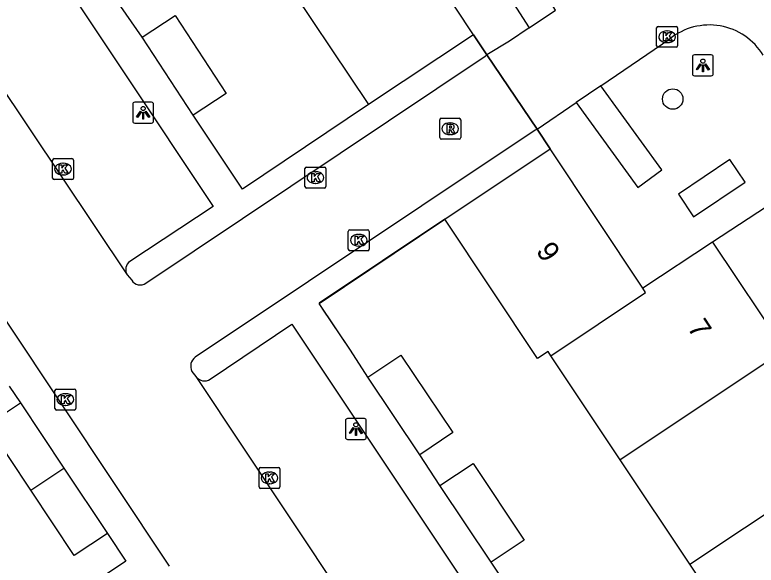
# Model space of a CAD drawing. Extents: x 158352 to 159489, y 383828 to 384597.
# Drawn here: x 158738.01 to 158773.43, y 384230.08 to 384256.39 of the extents above; entities that cross this region are included whole.
import ezdxf

# ---------------------------------------------------------------- set-up
doc = ezdxf.new("R2010")
doc.units = 0
for name, color, linetype in [('IMGEO_Boom', 7, 'Continuous'), ('IMGEO_Hek', 7, 'Continuous'), ('IMGEO_Kolk', 7, 'Continuous'), ('IMGEO_Lichtpunt', 7, 'Continuous'), ('IMGEO_Muur', 7, 'Continuous'), ('IMGEO_Pand', 7, 'Continuous'), ('IMGEO_Pand_nummerreeks', 7, 'Continuous'), ('IMGEO_Rijbaan_lokaal_open', 7, 'Continuous'), ('IMGEO_Rioolput', 7, 'Continuous'), ('IMGEO_Voetpad_open', 7, 'Continuous')]:
    doc.layers.add(name, color=color, linetype=linetype)

msp = doc.modelspace()

# ---------------------------------------------------------------- linework, layer by layer
at = {"layer": 'IMGEO_Boom'}
msp.add_circle((158769.446, 384252.366), 0.489, dxfattribs=at)
at = {"layer": 'IMGEO_Hek'}
for points in [[(158759.926, 384255.435), (158760.57, 384254.474)], [(158760.57, 384254.474), (158762.961, 384250.932)], [(158762.961, 384250.932), (158763.582, 384249.979)]]:
    msp.add_lwpolyline(points, dxfattribs=at)
at = {"layer": 'IMGEO_Kolk'}
for p, q in [((158768.677, 384254.916), (158768.677, 384255.768)), ((158768.752, 384255.842), (158769.604, 384255.842)), ((158769.165, 384255.622), (158769.19, 384255.622)), ((158769.678, 384255.768), (158769.678, 384254.916)), ((158769.604, 384254.842), (158768.752, 384254.842)), ((158769.188, 384255.062), (158769.163, 384255.062)), ((158739.884, 384249.516), (158740.736, 384249.516)), ((158739.809, 384248.59), (158739.809, 384249.442)), ((158740.297, 384249.296), (158740.322, 384249.296)), ((158740.81, 384249.442), (158740.81, 384248.59)), ((158751.871, 384248.186), (158751.871, 384249.038)), ((158751.946, 384249.112), (158752.798, 384249.112)), ((158752.359, 384248.892), (158752.384, 384248.892)), ((158752.872, 384249.038), (158752.872, 384248.186)), ((158740.736, 384248.516), (158739.884, 384248.516)), ((158740.32, 384248.736), (158740.295, 384248.736)), ((158752.798, 384248.112), (158751.946, 384248.112)), ((158752.382, 384248.332), (158752.357, 384248.332)), ((158753.943, 384245.189), (158753.943, 384246.041)), ((158754.018, 384246.115), (158754.87, 384246.115)), ((158754.944, 384246.041), (158754.944, 384245.189)), ((158754.431, 384245.895), (158754.456, 384245.895)), ((158754.454, 384245.335), (158754.429, 384245.335)), ((158754.87, 384245.115), (158754.018, 384245.115)), ((158739.921, 384237.573), (158739.921, 384238.425)), ((158739.996, 384238.499), (158740.848, 384238.499)), ((158740.409, 384238.279), (158740.434, 384238.279)), ((158740.922, 384238.425), (158740.922, 384237.573)), ((158740.848, 384237.499), (158739.996, 384237.499)), ((158740.432, 384237.719), (158740.407, 384237.719)), ((158749.675, 384233.827), (158749.675, 384234.679)), ((158749.75, 384234.753), (158750.602, 384234.753)), ((158750.676, 384234.679), (158750.676, 384233.827)), ((158750.163, 384234.533), (158750.188, 384234.533)), ((158750.186, 384233.973), (158750.161, 384233.973)), ((158750.602, 384233.753), (158749.75, 384233.753))]:
    msp.add_line(p, q, dxfattribs=at)
for points in [[(158768.677, 384254.916), (158768.677, 384255.768)], [(158768.752, 384255.842), (158769.604, 384255.842)], [(158768.998, 384255.542), (158769.121, 384255.542), (158769.121, 384255.391), (158769.251, 384255.542), (158769.415, 384255.542), (158769.269, 384255.391), (158769.422, 384255.142), (158769.27, 384255.142), (158769.185, 384255.306), (158769.121, 384255.239), (158769.121, 384255.142), (158768.998, 384255.142), (158768.998, 384255.542)], [(158769.678, 384255.768), (158769.678, 384254.916)], [(158769.604, 384254.842), (158768.752, 384254.842)], [(158739.884, 384249.516), (158740.736, 384249.516)], [(158739.809, 384248.59), (158739.809, 384249.442)], [(158740.13, 384249.216), (158740.253, 384249.216), (158740.253, 384249.065), (158740.383, 384249.216), (158740.547, 384249.216), (158740.401, 384249.065), (158740.554, 384248.816), (158740.402, 384248.816), (158740.317, 384248.98), (158740.253, 384248.913), (158740.253, 384248.816), (158740.13, 384248.816), (158740.13, 384249.216)], [(158740.81, 384249.442), (158740.81, 384248.59)], [(158751.871, 384248.186), (158751.871, 384249.038)], [(158751.946, 384249.112), (158752.798, 384249.112)], [(158752.192, 384248.812), (158752.315, 384248.812), (158752.315, 384248.661), (158752.445, 384248.812), (158752.609, 384248.812), (158752.463, 384248.661), (158752.616, 384248.412), (158752.464, 384248.412), (158752.379, 384248.576), (158752.315, 384248.509), (158752.315, 384248.412), (158752.192, 384248.412), (158752.192, 384248.812)], [(158752.872, 384249.038), (158752.872, 384248.186)], [(158740.736, 384248.516), (158739.884, 384248.516)], [(158752.798, 384248.112), (158751.946, 384248.112)], [(158753.943, 384245.189), (158753.943, 384246.041)], [(158754.018, 384246.115), (158754.87, 384246.115)], [(158754.944, 384246.041), (158754.944, 384245.189)], [(158754.264, 384245.815), (158754.387, 384245.815), (158754.387, 384245.664), (158754.517, 384245.815), (158754.681, 384245.815), (158754.535, 384245.664), (158754.688, 384245.415), (158754.536, 384245.415), (158754.451, 384245.579), (158754.387, 384245.512), (158754.387, 384245.415), (158754.264, 384245.415), (158754.264, 384245.815)], [(158754.87, 384245.115), (158754.018, 384245.115)], [(158739.921, 384237.573), (158739.921, 384238.425)], [(158739.996, 384238.499), (158740.848, 384238.499)], [(158740.242, 384238.199), (158740.365, 384238.199), (158740.365, 384238.048), (158740.495, 384238.199), (158740.659, 384238.199), (158740.513, 384238.048), (158740.666, 384237.799), (158740.514, 384237.799), (158740.429, 384237.963), (158740.365, 384237.896), (158740.365, 384237.799), (158740.242, 384237.799), (158740.242, 384238.199)], [(158740.922, 384238.425), (158740.922, 384237.573)], [(158740.848, 384237.499), (158739.996, 384237.499)], [(158749.675, 384233.827), (158749.675, 384234.679)], [(158749.75, 384234.753), (158750.602, 384234.753)], [(158750.676, 384234.679), (158750.676, 384233.827)], [(158749.996, 384234.453), (158750.119, 384234.453), (158750.119, 384234.302), (158750.249, 384234.453), (158750.413, 384234.453), (158750.267, 384234.302), (158750.42, 384234.053), (158750.268, 384234.053), (158750.183, 384234.217), (158750.119, 384234.15), (158750.119, 384234.053), (158749.996, 384234.053), (158749.996, 384234.453)], [(158750.602, 384233.753), (158749.75, 384233.753)]]:
    msp.add_lwpolyline(points, dxfattribs=at)
for centre, start, end in [((158768.754, 384255.766), 91.552, 178.448), ((158768.754, 384255.766), 91.552, 178.448), ((158769.602, 384255.766), 1.552, 88.448), ((158769.602, 384255.766), 1.552, 88.448), ((158768.754, 384254.918), 181.552, 268.448), ((158768.754, 384254.918), 181.552, 268.448), ((158769.602, 384254.918), 271.552, 358.448), ((158769.602, 384254.918), 271.552, 358.448), ((158739.886, 384249.44), 91.552, 178.448), ((158739.886, 384249.44), 91.552, 178.448), ((158740.734, 384249.44), 1.552, 88.448), ((158740.734, 384249.44), 1.552, 88.448), ((158751.948, 384249.036), 91.552, 178.448), ((158751.948, 384249.036), 91.552, 178.448), ((158752.796, 384249.036), 1.552, 88.448), ((158752.796, 384249.036), 1.552, 88.448), ((158739.886, 384248.592), 181.552, 268.448), ((158739.886, 384248.592), 181.552, 268.448), ((158740.734, 384248.592), 271.552, 358.448), ((158740.734, 384248.592), 271.552, 358.448), ((158751.948, 384248.188), 181.552, 268.448), ((158751.948, 384248.188), 181.552, 268.448), ((158752.796, 384248.188), 271.552, 358.448), ((158752.796, 384248.188), 271.552, 358.448), ((158754.02, 384246.039), 91.552, 178.448), ((158754.02, 384246.039), 91.552, 178.448), ((158754.868, 384246.039), 1.552, 88.448), ((158754.868, 384246.039), 1.552, 88.448), ((158754.02, 384245.191), 181.552, 268.448), ((158754.02, 384245.191), 181.552, 268.448), ((158754.868, 384245.191), 271.552, 358.448), ((158754.868, 384245.191), 271.552, 358.448), ((158739.998, 384238.423), 91.552, 178.448), ((158739.998, 384238.423), 91.552, 178.448), ((158740.846, 384238.423), 1.552, 88.448), ((158740.846, 384238.423), 1.552, 88.448), ((158739.998, 384237.575), 181.552, 268.448), ((158739.998, 384237.575), 181.552, 268.448), ((158740.846, 384237.575), 271.552, 358.448), ((158740.846, 384237.575), 271.552, 358.448), ((158749.752, 384234.677), 91.552, 178.448), ((158749.752, 384234.677), 91.552, 178.448), ((158750.6, 384234.677), 1.552, 88.448), ((158750.6, 384234.677), 1.552, 88.448), ((158749.752, 384233.829), 181.552, 268.448), ((158749.752, 384233.829), 181.552, 268.448), ((158750.6, 384233.829), 271.552, 358.448), ((158750.6, 384233.829), 271.552, 358.448)]:
    msp.add_arc(centre, 0.0765, start, end, dxfattribs=at)
for centre, major_axis, ratio, start_param, end_param in [((158769.164, 384255.342), (-0.387, 0.002), 0.722429, 4.712389, 7.853982), ((158769.189, 384255.342), (-0.39, 0.002), 0.717154, 1.570796, 4.712389), ((158740.296, 384249.016), (-0.387, 0.002), 0.722429, 4.712389, 7.853982), ((158740.321, 384249.016), (-0.39, 0.002), 0.717154, 1.570796, 4.712389), ((158752.358, 384248.612), (-0.387, 0.002), 0.722429, 4.712389, 7.853982), ((158752.383, 384248.612), (-0.39, 0.002), 0.717154, 1.570796, 4.712389), ((158754.43, 384245.615), (-0.387, 0.002), 0.722429, 4.712389, 7.853982), ((158754.455, 384245.615), (-0.39, 0.002), 0.717154, 1.570796, 4.712389), ((158740.408, 384237.999), (-0.387, 0.002), 0.722429, 4.712389, 7.853982), ((158740.433, 384237.999), (-0.39, 0.002), 0.717154, 1.570796, 4.712389), ((158750.162, 384234.253), (-0.387, 0.002), 0.722429, 4.712389, 7.853982), ((158750.187, 384234.253), (-0.39, 0.002), 0.717154, 1.570796, 4.712389)]:
    msp.add_ellipse(centre, major_axis=major_axis, ratio=ratio, start_param=start_param, end_param=end_param, dxfattribs=at)
at = {"layer": 'IMGEO_Lichtpunt'}
for p, q in [((158771.289, 384254.476), (158770.481, 384254.476)), ((158771.289, 384254.476), (158770.481, 384254.476)), ((158770.387, 384254.381), (158770.387, 384253.574)), ((158770.387, 384254.381), (158770.387, 384253.574)), ((158771.383, 384253.574), (158771.383, 384254.381)), ((158771.383, 384253.574), (158771.383, 384254.381)), ((158770.481, 384253.48), (158771.289, 384253.48)), ((158770.481, 384253.48), (158771.289, 384253.48)), ((158743.64, 384252.117), (158743.64, 384251.31)), ((158743.64, 384252.117), (158743.64, 384251.31)), ((158744.542, 384252.212), (158743.734, 384252.212)), ((158744.542, 384252.212), (158743.734, 384252.212)), ((158744.636, 384251.31), (158744.636, 384252.117)), ((158744.636, 384251.31), (158744.636, 384252.117)), ((158743.734, 384251.216), (158744.542, 384251.216)), ((158743.734, 384251.216), (158744.542, 384251.216)), ((158753.807, 384236.994), (158753.807, 384236.187)), ((158753.807, 384236.994), (158753.807, 384236.187)), ((158754.709, 384237.089), (158753.901, 384237.089)), ((158754.709, 384237.089), (158753.901, 384237.089)), ((158754.803, 384236.187), (158754.803, 384236.994)), ((158754.803, 384236.187), (158754.803, 384236.994)), ((158753.901, 384236.093), (158754.709, 384236.093)), ((158753.901, 384236.093), (158754.709, 384236.093))]:
    msp.add_line(p, q, dxfattribs=at)
for points in [[(158770.761, 384254.045), (158770.8, 384254.017), (158770.612, 384253.755), (158770.574, 384253.782), (158770.761, 384254.045)], [(158770.863, 384253.997), (158770.91, 384253.997), (158770.91, 384253.675), (158770.863, 384253.675), (158770.863, 384253.997)], [(158770.973, 384254.017), (158771.011, 384254.044), (158771.198, 384253.782), (158771.159, 384253.754), (158770.973, 384254.017)], [(158744.014, 384251.781), (158744.053, 384251.753), (158743.865, 384251.491), (158743.827, 384251.518), (158744.014, 384251.781)], [(158744.116, 384251.733), (158744.163, 384251.733), (158744.163, 384251.411), (158744.116, 384251.411), (158744.116, 384251.733)], [(158744.226, 384251.753), (158744.264, 384251.78), (158744.451, 384251.518), (158744.412, 384251.49), (158744.226, 384251.753)], [(158754.181, 384236.658), (158754.22, 384236.63), (158754.032, 384236.368), (158753.994, 384236.395), (158754.181, 384236.658)], [(158754.283, 384236.61), (158754.33, 384236.61), (158754.33, 384236.288), (158754.283, 384236.288), (158754.283, 384236.61)], [(158754.393, 384236.63), (158754.431, 384236.657), (158754.618, 384236.395), (158754.579, 384236.367), (158754.393, 384236.63)]]:
    msp.add_lwpolyline(points, dxfattribs=at)
for centre in [(158770.886, 384254.179), (158744.139, 384251.915), (158754.306, 384236.792)]:
    msp.add_circle(centre, 0.0994, dxfattribs=at)
for centre, start, end in [((158770.481, 384254.381), 90, 180), ((158770.481, 384254.381), 90, 180), ((158771.289, 384254.381), 0, 90), ((158771.289, 384254.381), 0, 90), ((158770.481, 384253.574), 180, 270), ((158770.481, 384253.574), 180, 270), ((158771.289, 384253.574), 270, 0), ((158771.289, 384253.574), 270, 360), ((158743.734, 384252.117), 90, 180), ((158743.734, 384252.117), 90, 180), ((158744.542, 384252.117), 0, 90), ((158744.542, 384252.117), 0, 90), ((158743.734, 384251.31), 180, 270), ((158743.734, 384251.31), 180, 270), ((158744.542, 384251.31), 270, 0), ((158744.542, 384251.31), 270, 360), ((158753.901, 384236.994), 90, 180), ((158753.901, 384236.994), 90, 180), ((158754.709, 384236.994), 0, 90), ((158754.709, 384236.994), 0, 90), ((158753.901, 384236.187), 180, 270), ((158753.901, 384236.187), 180, 270), ((158754.709, 384236.187), 270, 0), ((158754.709, 384236.187), 270, 360)]:
    msp.add_arc(centre, 0.0946, start, end, dxfattribs=at)
at = {"layer": 'IMGEO_Muur'}
for points in [[(158754.903, 384252.103), (158748.889, 384248.062), (158747.381, 384250.297)], [(158754.054, 384240.358), (158752.543, 384242.59), (158758.557, 384246.623)], [(158758.557, 384246.623), (158752.557, 384242.6)], [(158754.054, 384240.358), (158752.691, 384242.371)]]:
    msp.add_lwpolyline(points, dxfattribs=at)
at = {"layer": 'IMGEO_Pand'}
for points in [[(158759.926, 384255.435), (158755.506, 384262.112)], [(158750.839, 384259.277), (158750.964, 384259.082), (158750.465, 384258.749), (158754.903, 384252.103)], [(158744.096, 384255.329), (158745.673, 384256.358), (158748.107, 384252.627), (158746.53, 384251.598)], [(158746.53, 384251.598), (158744.096, 384255.329)], [(158759.926, 384255.435), (158754.903, 384252.103)], [(158758.557, 384246.623), (158763.582, 384249.979)], [(158768.012, 384243.32), (158763.582, 384249.979)], [(158763.624, 384240.093), (158763.486, 384240.292), (158762.986, 384239.96), (158758.557, 384246.623)], [(158771.344, 384245.523), (158768.012, 384243.32)], [(158771.344, 384245.523), (158774.797, 384240.358)], [(158763.624, 384240.093), (158768.148, 384243.116), (158768.012, 384243.32)], [(158774.797, 384240.358), (158766.937, 384235.12)], [(158754.871, 384239.063), (158756.447, 384240.124), (158758.936, 384236.423), (158757.36, 384235.363)], [(158766.937, 384235.12), (158763.624, 384240.093)], [(158757.36, 384235.363), (158754.871, 384239.063)], [(158738.77, 384233.665), (158736.691, 384236.783), (158738.272, 384237.837)], [(158738.272, 384237.837), (158740.351, 384234.719)], [(158770.27, 384230.127), (158778.142, 384235.374)], [(158770.27, 384230.127), (158766.937, 384235.12)], [(158738.77, 384233.665), (158740.351, 384234.719)], [(158740.351, 384234.719), (158742.43, 384231.601)], [(158758.322, 384233.895), (158759.903, 384234.949), (158762.351, 384231.275), (158760.77, 384230.221)], [(158742.43, 384231.601), (158740.849, 384230.547), (158738.77, 384233.665)], [(158760.77, 384230.221), (158758.322, 384233.895)], [(158773.591, 384225.148), (158770.27, 384230.127)]]:
    msp.add_lwpolyline(points, dxfattribs=at)
at = {"layer": 'IMGEO_Rijbaan_lokaal_open'}
for points in [[(158726.176, 384269.689), (158743.37, 384243.965)], [(158762.589, 384255.767), (158763.847, 384256.62)], [(158762.589, 384255.767), (158761.652, 384255.133), (158760.57, 384254.474)], [(158766.013, 384253.005), (158769.3, 384255.239)], [(158744.263, 384243.568), (158760.476, 384254.416), (158760.57, 384254.474)], [(158762.961, 384250.932), (158760.57, 384254.474)], [(158766.013, 384253.005), (158764.828, 384252.201)], [(158762.961, 384250.932), (158764.828, 384252.201)], [(158762.961, 384250.932), (158762.876, 384250.875), (158746.627, 384240.029)], [(158745.402, 384230.033), (158735.025, 384245.603)], [(158743.37, 384243.965), (158743.597, 384243.711)], [(158746.472, 384239.345), (158746.663, 384239.098)], [(158746.663, 384239.098), (158765.045, 384211.446)]]:
    msp.add_lwpolyline(points, dxfattribs=at)
for centre, radius, start, end in [((158771.193, 384252.892), 3.015, 31.2892, 128.885), ((158743.992, 384243.927), 0.45, 208.6552, 307.1083), ((158746.948, 384239.597), 0.539, 126.6135, 207.8504)]:
    msp.add_arc(centre, radius, start, end, dxfattribs=at)
at = {"layer": 'IMGEO_Rioolput'}
for p, q in [((158758.311, 384250.521), (158758.311, 384251.373)), ((158758.386, 384251.447), (158759.238, 384251.447)), ((158759.312, 384251.373), (158759.312, 384250.521)), ((158758.799, 384251.227), (158758.824, 384251.227)), ((158758.822, 384250.667), (158758.797, 384250.667)), ((158759.238, 384250.447), (158758.386, 384250.447))]:
    msp.add_line(p, q, dxfattribs=at)
for points in [[(158758.311, 384250.521), (158758.311, 384251.373)], [(158758.386, 384251.447), (158759.238, 384251.447)], [(158759.312, 384251.373), (158759.312, 384250.521)], [(158758.9, 384251.145), (158758.648, 384251.147), (158758.648, 384250.747)], [(158758.826, 384251.066), (158758.772, 384251.066), (158758.772, 384250.985)], [(158758.772, 384250.985), (158758.824, 384250.985)], [(158758.648, 384250.747), (158758.772, 384250.747), (158758.772, 384250.909), (158758.783, 384250.909)], [(158758.83, 384250.88), (158758.901, 384250.747), (158759.041, 384250.747), (158758.976, 384250.873)], [(158759.238, 384250.447), (158758.386, 384250.447)]]:
    msp.add_lwpolyline(points, dxfattribs=at)
for centre, radius, start, end in [((158758.388, 384251.371), 0.0765, 91.552, 178.448), ((158758.388, 384251.371), 0.0765, 91.552, 178.448), ((158759.236, 384251.371), 0.0765, 1.552, 88.448), ((158759.236, 384251.371), 0.0765, 1.552, 88.448), ((158758.808, 384251.174), 0.19, 274.7715, 282.9687), ((158758.832, 384250.97), 0.0964, 77.0061, 93.1865), ((158758.846, 384251.027), 0.0378, 276.6634, 79.6772), ((158758.899, 384251.035), 0.109, 350.3612, 89.416), ((158758.897, 384251.035), 0.112, 277.5842, 350.9817), ((158758.881, 384250.82), 0.108, 29.5134, 73.7905), ((158758.782, 384250.856), 0.0533, 26.0293, 88.6989), ((158758.388, 384250.523), 0.0765, 181.552, 268.448), ((158758.388, 384250.523), 0.0765, 181.552, 268.448), ((158759.236, 384250.523), 0.0765, 271.552, 358.448), ((158759.236, 384250.523), 0.0765, 271.552, 358.448)]:
    msp.add_arc(centre, radius, start, end, dxfattribs=at)
for centre, major_axis, ratio, start_param, end_param in [((158758.798, 384250.947), (-0.387, 0.002), 0.722429, 4.712389, 7.853982), ((158758.823, 384250.947), (-0.39, 0.002), 0.717154, 1.570796, 4.712389)]:
    msp.add_ellipse(centre, major_axis=major_axis, ratio=ratio, start_param=start_param, end_param=end_param, dxfattribs=at)
at = {"layer": 'IMGEO_Voetpad_open'}
for points in [[(158726.176, 384269.689), (158730.582, 384272.613), (158747.486, 384247.227), (158743.506, 384244.605)], [(158763.847, 384256.62), (158761.247, 384260.675), (158759.968, 384259.855), (158762.589, 384255.767)], [(158744.096, 384255.329), (158743.067, 384256.792)], [(158760.57, 384254.474), (158759.926, 384255.435)], [(158764.828, 384252.201), (158767.771, 384248.14), (158768.93, 384248.98), (158766.013, 384253.005)], [(158754.903, 384252.103), (158748.889, 384248.062), (158747.381, 384250.297), (158746.53, 384251.598)], [(158763.582, 384249.979), (158762.961, 384250.932)], [(158772.909, 384248.396), (158772.182, 384249.478), (158769.717, 384247.822), (158770.444, 384246.74), (158772.909, 384248.396)], [(158787.778, 384226.382), (158773.923, 384247.213), (158771.344, 384245.523)], [(158754.871, 384239.063), (158754.054, 384240.358), (158752.543, 384242.59), (158758.557, 384246.623)], [(158747.348, 384238.972), (158751.24, 384241.602), (158769.384, 384214.37), (158765.045, 384211.446)], [(158737.74, 384238.639), (158738.272, 384237.837)], [(158758.322, 384233.895), (158757.36, 384235.363)], [(158742.43, 384231.601), (158743.318, 384230.269), (158738.782, 384227.246), (158739.748, 384225.797)], [(158761.646, 384228.915), (158760.77, 384230.221)]]:
    msp.add_lwpolyline(points, dxfattribs=at)
for centre, radius, start, end in [((158743.793, 384244.21), 0.489, 125.9608, 210.0454), ((158747.073, 384239.402), 0.511, 216.5697, 302.5852)]:
    msp.add_arc(centre, radius, start, end, dxfattribs=at)

# ---------------------------------------------------------------- texts
at = {"layer": 'IMGEO_Pand_nummerreeks'}
for s, rotation, p in [('9', 303.9811, (158762.883, 384245.103)), ('7', 303.3023, (158770.118, 384241.432))]:
    msp.add_text(s, height=1, rotation=rotation, dxfattribs=at).set_placement(p)

doc.saveas('drawing.dxf')
